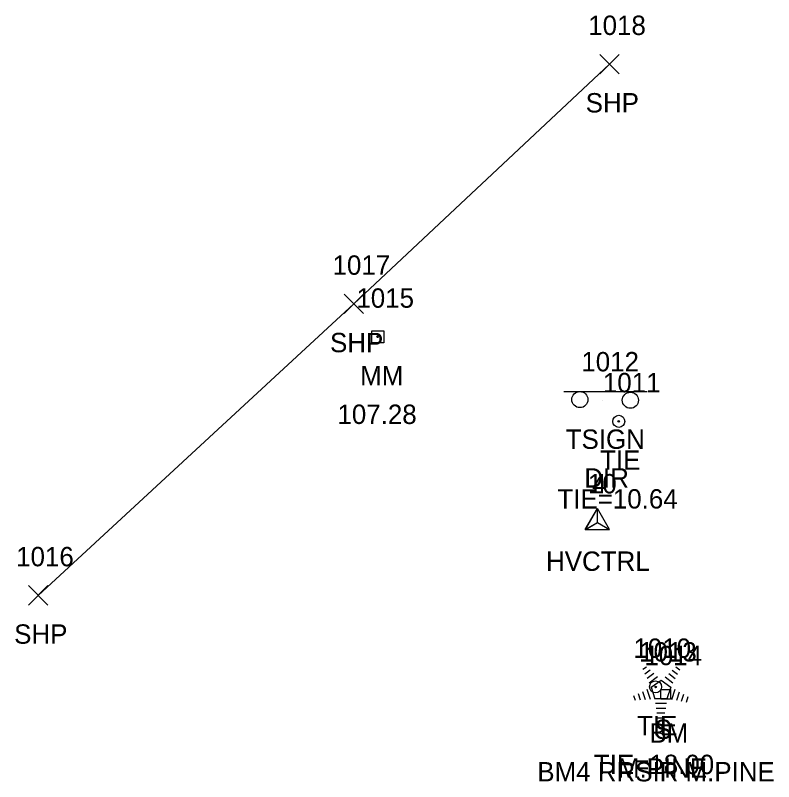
# Model space of a CAD drawing. Extents: x 1483143 to 1488182, y 802902 to 807581.
# Drawn here: x 1486165 to 1486243.3, y 803853.9 to 803933 of the extents above; entities that cross this region are included whole.
import ezdxf

# ---------------------------------------------------------------- set-up
doc = ezdxf.new("R2010")
doc.units = 0
for name, color, linetype in [('C_A', 7, 'Continuous'), ('C_C', 7, 'Continuous'), ('C_I', 7, 'Continuous'), ('CBP', 7, 'Continuous'), ('CPBM', 7, 'Continuous'), ('CPSM', 7, 'Continuous'), ('L_A', 7, 'Continuous'), ('L_C', 7, 'Continuous'), ('L_I', 7, 'Continuous'), ('LTC', 7, 'Continuous'), ('P_A', 7, 'Continuous'), ('P_I', 7, 'Continuous'), ('P_TIC', 7, 'Continuous'), ('PSP', 7, 'Continuous'), ('S_A', 7, 'Continuous'), ('S_C', 7, 'Continuous'), ('S_I', 7, 'Continuous'), ('SRM', 7, 'Continuous'), ('SSGN', 7, 'Continuous')]:
    doc.layers.add(name, color=color, linetype=linetype)

msp = doc.modelspace()

# ---------------------------------------------------------------- linework, layer by layer
at = {"layer": 'CBP'}
for centre, radius in [((1486227.332, 803891.069), 0.625), ((1486227.332, 803891.069), 0.0833), ((1486231.137, 803863.651), 0.625), ((1486231.137, 803863.651), 0.0833)]:
    msp.add_circle(centre, radius, dxfattribs=at)
at = {"layer": 'CPBM'}
for p, q in [((1486231.68, 803862.396), (1486231.68, 803863.396)), ((1486231.68, 803863.396), (1486232.68, 803863.396)), ((1486232.68, 803863.396), (1486232.68, 803862.396)), ((1486232.68, 803862.396), (1486231.68, 803862.396)), ((1486232.183, 803862.896), (1486232.183, 803862.896)), ((1486232.183, 803862.896), (1486232.183, 803862.896))]:
    msp.add_line(p, q, dxfattribs=at)
at = {"layer": 'CPSM'}
for p, q in [((1486223.88, 803879.913), (1486225.13, 803882.078)), ((1486223.887, 803879.917), (1486225.137, 803882.082)), ((1486226.38, 803879.913), (1486225.13, 803882.078)), ((1486225.13, 803880.634), (1486225.13, 803882.078)), ((1486226.387, 803879.917), (1486225.137, 803882.082)), ((1486225.137, 803880.638), (1486225.137, 803882.082)), ((1486223.88, 803879.913), (1486225.13, 803880.634)), ((1486223.887, 803879.917), (1486225.137, 803880.638)), ((1486225.13, 803880.634), (1486225.13, 803880.634)), ((1486225.13, 803880.634), (1486226.38, 803879.913)), ((1486225.137, 803880.638), (1486225.137, 803880.638)), ((1486225.137, 803880.638), (1486226.387, 803879.917)), ((1486223.88, 803879.913), (1486226.38, 803879.913)), ((1486223.887, 803879.917), (1486226.387, 803879.917))]:
    msp.add_line(p, q, dxfattribs=at)
at = {"layer": 'LTC'}
for p, q in [((1486229.833, 803865.481), (1486230.187, 803865.739)), ((1486230.042, 803865.016), (1486230.571, 803865.4)), ((1486232.86, 803865.373), (1486233.409, 803864.974)), ((1486233.231, 803865.722), (1486233.65, 803865.417)), ((1486230.252, 803864.55), (1486230.956, 803865.061)), ((1486230.461, 803864.084), (1486231.34, 803864.722)), ((1486232.118, 803864.677), (1486232.927, 803864.088)), ((1486232.489, 803865.025), (1486233.168, 803864.531)), ((1486230.686, 803863.629), (1486231.698, 803864.364)), ((1486231.698, 803864.364), (1486232.695, 803863.639)), ((1486229.321, 803862.977), (1486229.532, 803862.325)), ((1486229.776, 803863.194), (1486230.047, 803862.358)), ((1486230.231, 803863.41), (1486230.562, 803862.391)), ((1486230.686, 803863.629), (1486231.073, 803862.436)), ((1486232.695, 803863.639), (1486232.304, 803862.436)), ((1486233.132, 803863.368), (1486232.794, 803862.328)), ((1486233.577, 803863.117), (1486233.289, 803862.233)), ((1486228.865, 803862.76), (1486229.017, 803862.292)), ((1486232.304, 803862.436), (1486231.073, 803862.436)), ((1486234.021, 803862.867), (1486233.784, 803862.138)), ((1486234.466, 803862.617), (1486234.279, 803862.043)), ((1486232.265, 803861.936), (1486231.121, 803861.936)), ((1486232.181, 803861.436), (1486231.193, 803861.436)), ((1486232.098, 803860.936), (1486231.266, 803860.936)), ((1486232.014, 803860.436), (1486231.339, 803860.436))]:
    msp.add_line(p, q, dxfattribs=at)
at = {"layer": 'P_TIC'}
for points in [[(1486225.383, 803926.964), (1486227.383, 803928.964)], [(1486227.383, 803926.964), (1486225.383, 803928.964)], [(1486198.989, 803902.207), (1486200.989, 803904.207)], [(1486200.989, 803902.207), (1486198.989, 803904.207)], [(1486166.376, 803872.107), (1486168.376, 803874.107)], [(1486168.376, 803872.107), (1486166.376, 803874.107)]]:
    msp.add_lwpolyline(points, dxfattribs=at)
at = {"layer": 'PSP'}
msp.add_lwpolyline([(1486167.376, 803873.107), (1486199.989, 803903.207), (1486226.383, 803927.964)], dxfattribs=at)
at = {"layer": 'SRM'}
msp.add_lwpolyline([(1486201.824, 803900.427), (1486203.074, 803900.427), (1486203.074, 803899.177), (1486201.824, 803899.177)], close=True, dxfattribs=at)
msp.add_circle((1486202.449, 803899.802), 0.0833, dxfattribs=at)
at = {"layer": 'SSGN'}
for p, q in [((1486221.659, 803894.154), (1486230.256, 803894.154)), ((1486225.681, 803893.25), (1486225.681, 803893.25))]:
    msp.add_line(p, q, dxfattribs=at)
for centre in [(1486223.32, 803893.32), (1486228.535, 803893.25)]:
    msp.add_circle(centre, 0.833, dxfattribs=at)

# ---------------------------------------------------------------- texts
at = {"layer": 'C_A'}
for s, p in [('TIE', (1486225.411, 803886.069)), ('HVCTRL', (1486219.823, 803875.634)), ('HVCTRL', (1486219.83, 803875.638)), ('TIE', (1486229.216, 803858.651)), ('BM', (1486230.498, 803857.896))]:
    msp.add_text(s, height=2, dxfattribs=at).set_placement(p)
at = {"layer": 'C_C'}
for s, p in [('TIE=10.64', (1486221.001, 803882.069)), ('TIE=18.00', (1486224.767, 803854.651)), ('BM4 RRSIR M.PINE', (1486218.923, 803853.896))]:
    msp.add_text(s, height=2, dxfattribs=at).set_placement(p)
at = {"layer": 'C_I'}
for s, p in [('1011', (1486225.694, 803894.069)), ('10', (1486224.146, 803883.634)), ('4', (1486224.57, 803883.638)), ('1010', (1486228.845, 803866.651)), ('1014', (1486229.978, 803865.896))]:
    msp.add_text(s, height=2, dxfattribs=at).set_placement(p)
at = {"layer": 'L_A'}
msp.add_text('S', height=2, dxfattribs=at).set_placement((1486231.023, 803858.273))
at = {"layer": 'L_C'}
msp.add_text('M.PINE', height=2, dxfattribs=at).set_placement((1486227.244, 803854.273))
at = {"layer": 'L_I'}
msp.add_text('1013', height=2, dxfattribs=at).set_placement((1486229.433, 803866.273))
at = {"layer": 'LTC'}
msp.add_text('.', height=1.037, rotation=270, dxfattribs=at).set_placement((1486231.58, 803863.377))
at = {"layer": 'P_A'}
for p in [(1486223.919, 803922.964), (1486197.525, 803898.207), (1486164.912, 803868.107)]:
    msp.add_text('SHP', height=2, dxfattribs=at).set_placement(p)
at = {"layer": 'P_I'}
for s, p in [('1018', (1486224.179, 803930.964)), ('1017', (1486197.784, 803906.207)), ('1016', (1486165.116, 803876.107))]:
    msp.add_text(s, height=2, dxfattribs=at).set_placement(p)
at = {"layer": 'S_A'}
for s, p in [('MM', (1486200.638, 803894.802)), ('TSIGN', (1486221.857, 803888.232))]:
    msp.add_text(s, height=2, dxfattribs=at).set_placement(p)
at = {"layer": 'S_C'}
for s, p in [('107.28', (1486198.291, 803890.802)), ('DIR', (1486223.778, 803884.232))]:
    msp.add_text(s, height=2, dxfattribs=at).set_placement(p)
at = {"layer": 'S_I'}
for s, p in [('1015', (1486200.244, 803902.802)), ('1012', (1486223.471, 803896.232))]:
    msp.add_text(s, height=2, dxfattribs=at).set_placement(p)

doc.saveas('drawing.dxf')
